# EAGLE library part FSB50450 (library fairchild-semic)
Smart Power Module (SPM®) 500V 3.0A 3-phase FRFET inverter including high voltage integrated circuit (HVIC) Source: http://www.fairchildsemi.com/ds/FS/FSB50450.pdf
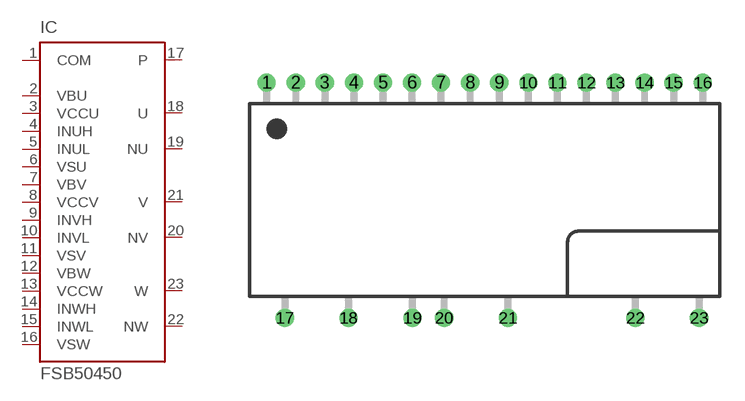
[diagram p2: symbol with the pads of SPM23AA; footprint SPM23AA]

Designator prefix IC

## FSB50450 (MPN: FSB50450S; OC_FARNELL: 1095107; OC_NEWARK: 67P3515)  [SPM23AA]
1  COM  in
2  VBU  in
3  VCCU  in
4  INUH  in
5  INUL  in
6  VSU  in
7  VBV  in
8  VCCV  in
9  INVH  in
10  INVL  in
11  VSV  in
12  VBW  in
13  VCCW  in
14  INWH  in
15  INWL  in
16  VSW  in
17  P  in
18  U  in
19  NU  in
20  NV  in
21  V  in
22  NW  in
23  W  in

## Footprint SPM23AA (pad centres in mm)
Source: http://www.fairchildsemi.com/ds/FS/FSB50450.pdf
drill 0.6 pad 1 round: 1 -13.34,7.2; 2 -11.561,7.2; 3 -9.783,7.2; 4 -8.004,7.2; 5 -6.226,7.2; 6 -4.447,7.2; 7 -2.668,7.2; 8 -0.89,7.2; 9 0.889,7.2; 10 2.667,7.2; 11 4.446,7.2; 12 6.225,7.2; 13 8.003,7.2; 14 9.782,7.2; 15 11.56,7.2; 16 13.339,7.2; 17 -12.23,-7.2; 18 -8.33,-7.2; 19 -4.43,-7.2; 20 -2.48,-7.2; 21 1.42,-7.2; 22 9.22,-7.2; 23 13.12,-7.2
